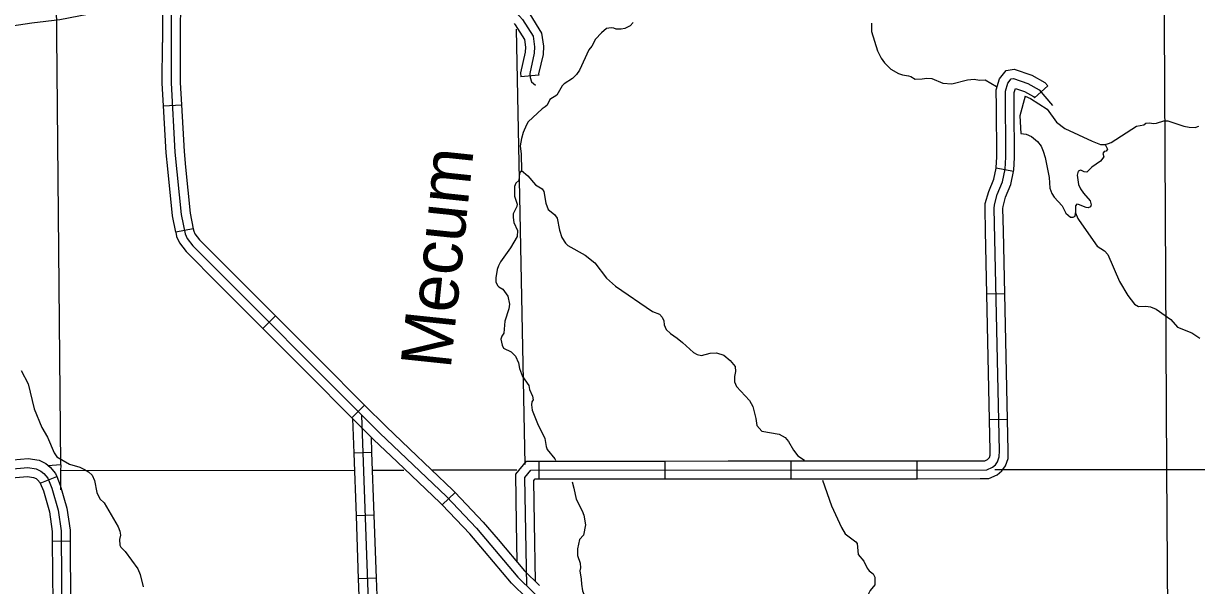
# Model space of a CAD drawing. Extents: x 1212896 to 1368412, y 378476 to 478763.
# Drawn here: x 1279495 to 1289328, y 394792 to 399509 of the extents above; entities that cross this region are included whole.
import ezdxf

# ---------------------------------------------------------------- set-up
doc = ezdxf.new("R2010")
doc.units = 0
for name, color, linetype in [('Level 10', 7, 'Continuous'), ('Level 31', 7, 'Continuous'), ('Level 32', 7, 'Continuous'), ('Level 35', 7, 'Continuous'), ('Level 4', 7, 'Continuous'), ('Level 45', 7, 'Continuous'), ('Level 5', 7, 'Continuous')]:
    doc.layers.add(name, color=color, linetype=linetype)

msp = doc.modelspace()

# ---------------------------------------------------------------- linework, layer by layer
at = {"layer": 'Level 10'}
msp.add_lwpolyline([(1281619.9, 400108.4), (1281398.4, 400000.5), (1281131.3, 399895.1), (1281022.8, 399844.3), (1280743.8, 399750), (1280435.5, 399662.9), (1279799.2, 399539.1), (1279564.6, 399512.7), (1279321.2, 399475.8), (1278911.3, 399400.6), (1278500.3, 399341.5), (1278433.7, 399324.8), (1278349.5, 399295.5), (1278229.7, 399230.3), (1278119.2, 399158.5), (1278036, 399113.9), (1277928.1, 399062.6), (1277745.3, 398994.3), (1277642.4, 398960.1)], dxfattribs=at)
at = {"layer": 'Level 31'}
for p, q in [((1280668.7, 398818.1), (1280818.4, 398826.6)), ((1280818.4, 398826.6), (1280818.4, 398826.6)), ((1280918.5, 397786.9), (1280771.3, 397757.9)), ((1280771.3, 397757.9), (1280771.3, 397757.9)), ((1281501.3, 396948.7), (1281607.6, 397054.6)), ((1282353.2, 396306.9), (1282247, 396201)), ((1282247, 396201), (1282247, 396201)), ((1282247, 396201), (1282247, 396201)), ((1282626.3, 395830.9), (1282626.3, 395830.9)), ((1283005.4, 395468.7), (1283114, 395572.1))]:
    msp.add_line(p, q, dxfattribs=at)
for points in [[(1280733.7, 399878), (1280731.6, 399010.9), (1280764.3, 398428.3), (1280817.1, 397906), (1280849.2, 397743.5), (1280866, 397705.8), (1280913.3, 397642.7), (1282480.5, 396071.1), (1283040, 395539.1), (1283292.4, 395273.9), (1283638.6, 394863.5), (1284918.5, 393609.4)], [(1280659.7, 399726.2), (1280658.8, 399350.2)], [(1280809.8, 399772.3), (1280808.8, 399349.8)], [(1280668.7, 398818.1), (1280657.9, 399008.9), (1280658.8, 399350.2)], [(1280808.8, 399349.8), (1280807.9, 399013), (1280818.4, 398826.6)], [(1280818.4, 398826.6), (1280840.5, 398434.2), (1280853.7, 398303.3)], [(1280704.5, 398288.2), (1280690.9, 398422.5), (1280668.7, 398818.1)], [(1280771.3, 397757.9), (1280744.2, 397895.2), (1280704.5, 398288.2)], [(1280853.7, 398303.3), (1280892.7, 397917.3), (1280918.5, 397786.9)], [(1280771.3, 397757.9), (1280778.5, 397721.1), (1280802.1, 397668.3), (1280857.5, 397594.4), (1281128.5, 397322.6)], [(1280918.5, 397786.9), (1280922.4, 397766.7), (1280932.2, 397744.7), (1280971.1, 397692.8), (1281234.7, 397428.5)], [(1281234.7, 397428.5), (1281607.6, 397054.6)], [(1281501.3, 396948.7), (1281128.5, 397322.6)], [(1281607.6, 397054.6), (1281980.4, 396680.8)], [(1281874.2, 396574.9), (1281501.3, 396948.7)], [(1281980.4, 396680.8), (1282353.2, 396306.9)], [(1282247, 396201), (1281874.2, 396574.9)], [(1282353.2, 396306.9), (1282533.9, 396125.8), (1282729.7, 395939.6)], [(1282247, 396201), (1282429.1, 396018.4), (1282626.3, 395830.9)], [(1282729.7, 395939.6), (1283094.1, 395593.1), (1283114, 395572.1)], [(1283005.4, 395468.7), (1282988, 395487), (1282626.3, 395830.9)], [(1283114, 395572.1), (1283349.3, 395324.9), (1283472.6, 395178.7)], [(1283358, 395082), (1283237.5, 395224.8), (1283005.4, 395468.7)], [(1283472.6, 395178.7), (1283694.7, 394915.5), (1283820.7, 394792.1)], [(1283715.7, 394684.9), (1283584.6, 394813.4), (1283358, 395082)]]:
    msp.add_lwpolyline(points, dxfattribs=at)
at = {"layer": 'Level 32'}
for p, q in [((1282415.7, 395909.2), (1282265.8, 395903.8)), ((1279634.9, 395651.6), (1279773.7, 395708.4)), ((1282434.8, 395381.6), (1282284.9, 395376.1)), ((1279736.4, 395165.8), (1279886.4, 395166.8)), ((1282453.9, 394853.9), (1282304, 394848.5))]:
    msp.add_line(p, q, dxfattribs=at)
for points in [[(1282265.8, 395903.8), (1282255.3, 396192.7)], [(1282398.6, 394347.3), (1282330.7, 396220.3)], [(1282415.7, 395909.2), (1282411.1, 396036.5)], [(1282284.9, 395376.1), (1282265.8, 395903.8)], [(1282434.8, 395381.6), (1282415.7, 395909.2)], [(1274482.7, 395333.4), (1279532.2, 395782.8), (1279602.1, 395770.8), (1279639.8, 395752.2), (1279665.4, 395731.4), (1279697.7, 395692.6), (1279731.4, 395610.1), (1279784.3, 395425), (1279809.4, 395251.7), (1279823.5, 393145.8)], [(1279209.2, 395830.7), (1279535.3, 395859.7), (1279625.9, 395844.2), (1279681.2, 395816.9), (1279719.3, 395786.1), (1279763.9, 395732.3), (1279773.7, 395708.4)], [(1279222.5, 395681.3), (1279529.2, 395708.6), (1279579.1, 395700), (1279599.8, 395689.8), (1279613.4, 395678.8), (1279633.8, 395654.3), (1279634.9, 395651.6)], [(1279773.7, 395708.4), (1279803.7, 395635.2), (1279859.2, 395441.1), (1279885.7, 395257.4), (1279886.4, 395166.8)], [(1279634.9, 395651.6), (1279661.7, 395586), (1279712.2, 395409.6), (1279735.8, 395246.2), (1279736.4, 395165.8)], [(1282453.9, 394853.9), (1282434.8, 395381.6)], [(1282304, 394848.5), (1282284.9, 395376.1)], [(1279736.4, 395165.8), (1279739.9, 394637.8)], [(1279886.4, 395166.8), (1279889.9, 394638.8)], [(1282320.1, 394331.7), (1282322.1, 394349.9), (1282304, 394848.5)], [(1282469.3, 394316), (1282472.3, 394344.7), (1282453.9, 394853.9)]]:
    msp.add_lwpolyline(points, dxfattribs=at)
at = {"layer": 'Level 35'}
for points in [[(1284606.3, 399517), (1284579, 399488.9), (1284535.8, 399467.5), (1284505.8, 399462.2), (1284463.8, 399462.3), (1284443.7, 399469.9), (1284420.7, 399471.4), (1284382.9, 399466.6), (1284338.8, 399431.5), (1284289.5, 399376), (1284258.4, 399318.5), (1284233.2, 399286.9), (1284155.1, 399116.8), (1284129.9, 399080.1), (1284097.7, 399048.4), (1284026.8, 399003.7), (1284009.9, 398986.3), (1283964.6, 398908.6), (1283907, 398869.6), (1283883.1, 398824.2), (1283868.4, 398808.8), (1283842.8, 398793.2), (1283725.5, 398683.4), (1283710.1, 398659), (1283684.6, 398593.3)], [(1286602.3, 399511), (1286603.8, 399442.9), (1286654.3, 399279.6), (1286684.5, 399219.2), (1286711.4, 399177.6), (1286764.5, 399124.7), (1286829.1, 399088), (1286862.3, 399077.7), (1286912.3, 399070.8), (1286931.4, 399064.2), (1286968.9, 399040.9), (1287026.7, 399043.2), (1287065.5, 399050.1), (1287107.4, 399047), (1287200.1, 399008.9), (1287276.1, 399003.5), (1287407.9, 399036.1), (1287462.8, 399040.7), (1287506.9, 399034.6), (1287554.8, 399035.7), (1287651.6, 398979)], [(1287892.2, 398897.6), (1287845.9, 398734.2), (1287855.2, 398585.1), (1287899.4, 398579.1), (1287943.5, 398560.9), (1287995.3, 398519), (1288024.2, 398478.5), (1288043, 398438.8), (1288059.2, 398383), (1288091.8, 398216.4), (1288097.7, 398127.3), (1288113.4, 398081.4), (1288134.3, 398050.9), (1288200.8, 397978.2), (1288232.1, 397916.7), (1288271.7, 397883.5), (1288292.6, 397882.8), (1288309.5, 397892.3), (1288311.8, 397920.5), (1288331.9, 397873.4), (1288342.9, 397856.6)], [(1287892.2, 398897.6), (1287934.5, 398879.5), (1288075.2, 398789.4), (1288152.5, 398680.8), (1288223.5, 398627.2), (1288453.4, 398520), (1288522.8, 398494.4), (1288561.7, 398494.3), (1288590.5, 398500.9), (1288611.3, 398510.3)], [(1288611.3, 398510.3), (1288824.4, 398645.9), (1288885.3, 398658.8), (1288903, 398671.2), (1288936.8, 398674), (1288963.8, 398670.5)], [(1288963.8, 398670.5), (1288991.2, 398673.5), (1289054.2, 398690.6), (1289086.4, 398692.3), (1289219.8, 398648.1), (1289265.9, 398638), (1289314.9, 398636.1), (1289347.5, 398647.8)], [(1283684.6, 398593.3), (1283669.7, 398544.9), (1283659.1, 398482.5), (1283665.6, 398413.5), (1283668.6, 398274.2), (1283652.7, 398253), (1283646.5, 398191.5), (1283623, 398168), (1283609.7, 398140.6), (1283611.4, 398060.4), (1283632.9, 397992.8), (1283631.3, 397971.7), (1283599.7, 397912.8), (1283600.4, 397879.8), (1283606.3, 397839.8), (1283635.4, 397771), (1283631.8, 397722.1), (1283576, 397626.7), (1283493.8, 397509.6), (1283476.6, 397476.1), (1283464.3, 397444.8), (1283454.9, 397373.7), (1283454.4, 397339.5), (1283467.2, 397310.5), (1283478.5, 397298.8), (1283513.8, 397279.5), (1283556, 397221.3), (1283568.5, 397152.4), (1283564.3, 397114.2), (1283528.6, 397012.2), (1283521.5, 396911.5), (1283504.1, 396883.6), (1283496.7, 396859.4), (1283506.2, 396809.2), (1283518.7, 396785.4), (1283582.2, 396754.7), (1283619.4, 396718.2), (1283645.1, 396659.9), (1283653.1, 396613.9), (1283677.6, 396546.3), (1283732.1, 396471.3), (1283736.8, 396438.4), (1283761.8, 396380.6), (1283765.7, 396349.8), (1283756, 396333.8), (1283751.8, 396310.1), (1283759.6, 396263.4), (1283802, 396151.1), (1283865.6, 396027.2), (1283875.1, 395959.2), (1283885.6, 395933.4), (1283949.6, 395854.4), (1283954.6, 395845)], [(1288561.7, 398494.3), (1288580.2, 398454.9), (1288570.9, 398438.3), (1288552.3, 398433.5), (1288542.6, 398418.8), (1288550, 398390.8), (1288522.9, 398354.1), (1288449.1, 398302.3), (1288406.6, 398261.3), (1288386.5, 398263.6), (1288357.1, 398277.3), (1288336.1, 398270.8), (1288325.9, 398235.5), (1288338.6, 398157.6), (1288355.3, 398120.9), (1288380.1, 398085.3), (1288436.4, 398019.4), (1288445.1, 397986.5), (1288437.5, 397969.3), (1288418.7, 397961.9), (1288401.7, 397964.5), (1288339.2, 397990.2), (1288323.2, 397991.9), (1288311.6, 397978.6), (1288311.8, 397920.5)], [(1283668.6, 398274.2), (1283721.4, 398229.4), (1283788, 398155.5), (1283843.6, 398120.6), (1283857.1, 398098.9), (1283874.2, 398000), (1283893.3, 397948.3), (1283945.2, 397906), (1283967.8, 397873.8), (1283988.9, 397773.9), (1284007.2, 397714.3), (1284039.2, 397664.8), (1284057.6, 397645.2), (1284203.1, 397564.2), (1284283.3, 397500.8), (1284383, 397370.6), (1284458.4, 397305.3), (1284768.3, 397092.4), (1284825.4, 397069.9), (1284849.6, 397045.1), (1284862.2, 397012.5), (1284866.4, 396979.4), (1284882.4, 396941.5), (1284917.1, 396906.2), (1284972.8, 396869.3), (1285018.5, 396832.2), (1285111.2, 396747), (1285141.8, 396730.7), (1285177.1, 396723.9), (1285251, 396741.1), (1285304.4, 396744.4), (1285365.1, 396724.5), (1285418, 396679.6), (1285459, 396629.3), (1285463.9, 396587.3), (1285453.9, 396547), (1285453.8, 396501.9), (1285472.7, 396462.2), (1285580, 396346.3), (1285609.1, 396294.8), (1285633.2, 396194.1), (1285641.5, 396136.2), (1285682.7, 396087.2), (1285827.9, 396063), (1285878.2, 396034.1), (1285906.9, 396000.6), (1285948.4, 395928.4), (1285985.4, 395880), (1286042.3, 395844.1)], [(1288342.9, 397856.6), (1288493.5, 397640.9), (1288555.2, 397602.1), (1288583.8, 397570.7), (1288681.6, 397344.3), (1288753, 397226.5), (1288806.5, 397154.5), (1288839.9, 397133.2), (1288901.7, 397137.6), (1288940.8, 397131.1), (1288988.9, 397112.3), (1289111.1, 397024.1), (1289168, 396960), (1289288.6, 396913.7), (1289354.7, 396866.8)], [(1279476.2, 396596.9), (1279534.6, 396483.9), (1279583.1, 396276.4), (1279649.4, 396118.5), (1279696.1, 396038.3), (1279751.8, 395906.3), (1279774.6, 395871.7), (1279879.7, 395809.8), (1279968, 395785.7), (1280007.4, 395766.5), (1280039.8, 395745.1), (1280069.3, 395717.7), (1280089.2, 395674.1), (1280109.4, 395574.3), (1280135.5, 395519.7), (1280170.2, 395485.4), (1280287.4, 395284.5), (1280301.2, 395247.7), (1280306.9, 395215.7), (1280298.7, 395178.5), (1280301.8, 395130.4), (1280311.1, 395114.6), (1280347.8, 395077.3), (1280453.8, 394932.3), (1280473.8, 394883.6), (1280497, 394780.8)], [(1286192.5, 395676.1), (1286268, 395460.2), (1286351.9, 395278.6), (1286382.9, 395227.2), (1286471.2, 395159.9), (1286481.5, 395144.1), (1286490.5, 395054.1), (1286538.9, 394997.6), (1286567.3, 394939.2), (1286584.1, 394915.5), (1286616.2, 394890.8), (1286630.4, 394861.7), (1286630.8, 394798.6), (1286591, 394749.6), (1286571.2, 394710.1), (1286569.1, 394636.4), (1286559.3, 394603.5), (1286539, 394571), (1286538.8, 394533.9)], [(1284093.1, 395662.3), (1284109.3, 395609.5), (1284126.3, 395517.7), (1284177.3, 395419.6)], [(1284177.3, 395419.6), (1284191.1, 395383.8), (1284206.8, 395301.9), (1284188.8, 395214.3), (1284155.7, 395177.5), (1284137.4, 395100.4), (1284139.6, 395044.9), (1284160, 394981.1), (1284162.8, 394942.1), (1284158.4, 394915), (1284169.9, 394845), (1284170.8, 394804), (1284181.6, 394748.9), (1284229.6, 394625.8), (1284238.1, 394563.4), (1284264.3, 394502.3), (1284256.5, 394446), (1284243.3, 394412.6), (1284240.5, 394375.4)]]:
    msp.add_lwpolyline(points, dxfattribs=at)
at = {"layer": 'Level 4'}
for points in [[(1279807.2, 395805.4), (1279761.5, 400914.2)], [(1279807.2, 395805.4), (1279805.4, 395755.2), (1279806.5, 395596.4)]]:
    msp.add_lwpolyline(points, dxfattribs=at)
at = {"layer": 'Level 45'}
for p, q in [((1283814, 399076.3), (1283664.9, 399060.3)), ((1287968.2, 398886.3), (1288081.8, 398984.3)), ((1287793.8, 398266.9), (1287646.7, 398296.1)), ((1287720.3, 397241.2), (1287570.4, 397238)), ((1287743, 396185.4), (1287593, 396182.2)), ((1283816.7, 395686.4), (1283816.6, 395836.4)), ((1284872.7, 395687.3), (1284872.6, 395837.3)), ((1285928.7, 395688.1), (1285928.6, 395838.1)), ((1286984.7, 395689), (1286984.5, 395839))]:
    msp.add_line(p, q, dxfattribs=at)
for points in [[(1282073.5, 400679), (1282225.1, 400665.4), (1282274.2, 400654.4), (1282301.4, 400642), (1282339.2, 400602.7), (1282345.7, 400577.8), (1282343.3, 400505.6), (1282276, 399890.7), (1282280.3, 399829.6), (1282285.8, 399808.7), (1282300.1, 399794), (1282346.3, 399777.9), (1283586.7, 399779), (1283616.4, 399743.5), (1283621.8, 399636.4), (1283628.6, 399599.4), (1283678.7, 399543.4), (1283766.6, 399402), (1283779.5, 399314.1), (1283776.7, 399258.9), (1283738.5, 399089.6), (1283742.3, 399054.6), (1283753.1, 399018.8), (1283786.6, 398992.5)], [(1283718.5, 399609.3), (1283737.8, 399587.7), (1283837.2, 399427.8), (1283853.4, 399317.6), (1283850, 399248.8), (1283813, 399085.4), (1283814, 399076.3)], [(1283606.7, 399509.3), (1283617.3, 399497.4), (1283693.4, 399375.2), (1283702.9, 399310.4), (1283700.8, 399269.3), (1283661.2, 399094.1), (1283664.9, 399060.3)], [(1287649.9, 398808.5), (1287649, 398951.9), (1287675.8, 399043.5), (1287731.2, 399113.6), (1287799.8, 399126.6), (1287946.2, 399075.4), (1288056.7, 399013.4), (1288081.8, 398984.3)], [(1283713.4, 394790.2), (1283698.2, 395698.8), (1283748.5, 395760), (1287570.2, 395763), (1287617.1, 395785.1), (1287641.4, 395805), (1287660, 395831.4), (1287674.1, 395871.8), (1287675, 395921.9), (1287631.3, 397955.8), (1287632.7, 397985.9), (1287657.7, 398074.7), (1287701.3, 398178.9), (1287722.9, 398287.6), (1287728.7, 398386.9), (1287725.5, 398941.2), (1287745, 399007.8), (1287773.5, 399043.9), (1287793.9, 399047.7), (1287914.7, 399005.5), (1288007.6, 398953.4), (1288121.3, 398821.5)], [(1287799.9, 398809.3), (1287799.2, 398930.8), (1287809, 398964.4), (1287884.3, 398938.1), (1287960.3, 398895.5), (1287968.2, 398886.3)], [(1287646.7, 398296), (1287646.9, 398297.3), (1287652.3, 398389), (1287649.9, 398808.5)], [(1287793.8, 398266.9), (1287796.1, 398278.2), (1287802.3, 398385), (1287799.9, 398809.3)], [(1287559, 397765.8), (1287554.9, 397956.7), (1287556.8, 397998.1), (1287585.4, 398099.9), (1287627.9, 398201.3), (1287646.7, 398296.1)], [(1287709, 397769.1), (1287705, 397955), (1287705.8, 397974.1), (1287727.3, 398050.4), (1287772.1, 398157.3), (1287793.8, 398266.9)], [(1287570.4, 397238), (1287559, 397765.8)], [(1287720.3, 397241.2), (1287709, 397769.1)], [(1287581.7, 396710.1), (1287570.4, 397238)], [(1287731.7, 396713.3), (1287720.3, 397241.2)], [(1287593, 396182.2), (1287581.7, 396710.1)], [(1287743, 396185.4), (1287731.7, 396713.3)], [(1287512.5, 395839.4), (1287553.1, 395839.4), (1287576, 395850.2), (1287584.9, 395857.5), (1287591.4, 395866.6), (1287597.9, 395885.5), (1287598.6, 395921.8), (1287593, 396182.2)], [(1287512.7, 395689.4), (1287586.7, 395689.4), (1287656.7, 395722.4), (1287695.8, 395754.4), (1287726.1, 395797.5), (1287747.4, 395858.7), (1287748.6, 395922), (1287743, 396185.4)], [(1283628.2, 395316.9), (1283621.4, 395725.6), (1283712.3, 395836.4), (1283816.6, 395836.4)], [(1283816.6, 395836.4), (1284344.6, 395836.9)], [(1284344.6, 395836.9), (1284872.6, 395837.3)], [(1284872.6, 395837.3), (1285400.6, 395837.7)], [(1285400.6, 395837.7), (1285928.6, 395838.1)], [(1285928.6, 395838.1), (1286456.6, 395838.5)], [(1286456.6, 395838.5), (1286984.5, 395839)], [(1286984.5, 395839), (1287512.5, 395839.4)], [(1283778.2, 395319.4), (1283772.3, 395673), (1283783.3, 395686.4), (1283816.7, 395686.4)], [(1283816.7, 395686.4), (1284344.7, 395686.9)], [(1284344.7, 395686.9), (1284872.7, 395687.3)], [(1284872.7, 395687.3), (1285400.7, 395687.7)], [(1285400.7, 395687.7), (1285928.7, 395688.1)], [(1285928.7, 395688.1), (1286456.7, 395688.5)], [(1286456.7, 395688.5), (1286984.7, 395689)], [(1286984.7, 395689), (1287512.7, 395689.4)], [(1283633.7, 394987.8), (1283628.2, 395316.9)], [(1283786.5, 394825.6), (1283778.2, 395319.4)]]:
    msp.add_lwpolyline(points, dxfattribs=at)
at = {"layer": 'Level 5'}
for points in [[(1289046.7, 401121.9), (1289076.7, 395763.7)], [(1283623.7, 399460.3), (1283696.1, 395809)], [(1279807.2, 395805.4), (1279699.8, 395795.8)], [(1282267.2, 395758.3), (1279805.4, 395755.2)], [(1282683.6, 395758.8), (1282422.4, 395758.4)], [(1283629.1, 395759.9), (1282923.4, 395759.1)], [(1289076.7, 395763.7), (1287637.5, 395762.7)], [(1289076.7, 395763.7), (1289113.2, 390562.5)], [(1292430.9, 395762.2), (1289076.7, 395763.7)]]:
    msp.add_lwpolyline(points, dxfattribs=at)

# ---------------------------------------------------------------- texts
at = {"layer": 'Level 35'}
msp.add_text('Mecum', height=422.4, rotation=83.99323, dxfattribs=at).set_placement((1283074.7, 396602.5))

doc.saveas('drawing.dxf')
